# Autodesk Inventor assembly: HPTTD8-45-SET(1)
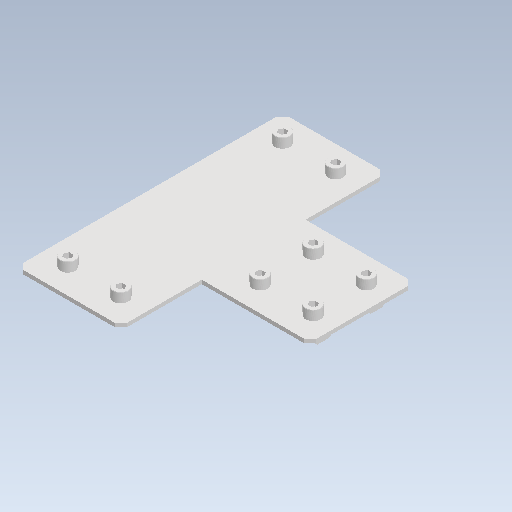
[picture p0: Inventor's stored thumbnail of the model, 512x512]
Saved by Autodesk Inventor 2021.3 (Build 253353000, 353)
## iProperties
Created: 2022-02
Part Number: HPTTD8-45-SET(1)
Document SubType Name: Assembly
Designer: kengo
Author: kengo
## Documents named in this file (4)
- C:\Users\kengo\Documents\S2S_frame\SDC345\frame_misumi_ver12\HPTTD8-45-SET(1).iam
- C:\Users\kengo\Documents\S2S_frame\SDC345\frame_misumi_ver12\HPTTD8-45.ipt
- C:\Users\kengo\Documents\S2S_frame\SDC345\frame_misumi_ver12\HNTT8-8.ipt
- C:\Users\kengo\Documents\S2S_frame\SDC345\frame_misumi_ver12\CBM8-15.ipt
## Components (17 placed, 3 different names)
1. HPTTD8-45
2. HNTT8-8
3. CBM8-15
4. HNTT8-8:1
5. CBM8-15:1
6. HNTT8-8:2
7. CBM8-15:2
8. HNTT8-8:3
9. CBM8-15:3
10. HNTT8-8:4
11. CBM8-15:4
12. HNTT8-8:5
13. CBM8-15:5
14. HNTT8-8:6
15. CBM8-15:6
16. HNTT8-8:7
17. CBM8-15:7
